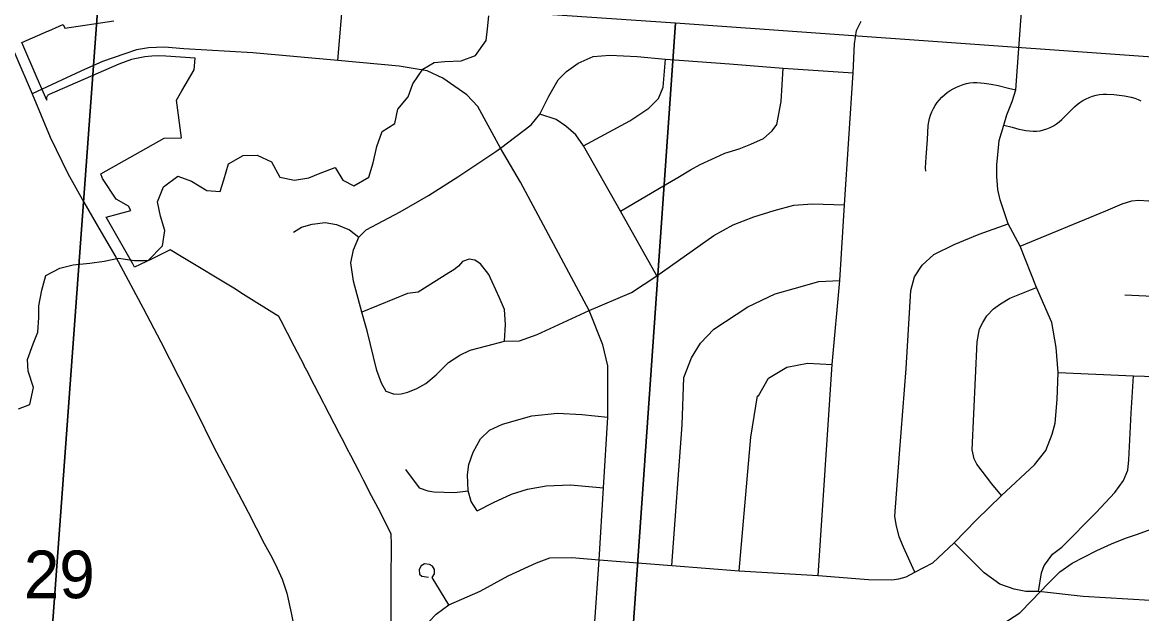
# Model space of a CAD drawing. Extents: x 0 to 34, y 0 to 26.1.
# Drawn here: x 25.117 to 26.1, y 16.628 to 17.147 of the extents above; entities that cross this region are included whole.
import ezdxf

# ---------------------------------------------------------------- set-up
doc = ezdxf.new("R2010")
doc.units = 0
for name, color, linetype in [('GM_X_Minor_River', 7, 'Continuous'), ('GM_X_Section', 7, 'Continuous'), ('GM_X_Section_Text', 7, 'Continuous'), ('GM_X_State_Route', 7, 'Continuous'), ('GM_X_Township_Road', 7, 'Continuous'), ('SC_Scratch1', 7, 'Continuous')]:
    doc.layers.add(name, color=color, linetype=linetype)

msp = doc.modelspace()

# ---------------------------------------------------------------- linework, layer by layer
at = {"layer": 'GM_X_Minor_River'}
for points in [[(25.11324, 16.80738), (25.12314, 16.81142), (25.12638, 16.82618), (25.12166, 16.84067), (25.12105, 16.85092), (25.12616, 16.86452), (25.13009, 16.87471), (25.13103, 16.88761), (25.13118, 16.89785), (25.13365, 16.91186), (25.13724, 16.92472), (25.14944, 16.93101), (25.16121, 16.93388), (25.17599, 16.93557), (25.18851, 16.93729), (25.20103, 16.93978), (25.215, 16.93769), (25.22712, 16.9379), (25.23979, 16.95063), (25.24187, 16.96427), (25.23789, 16.97685), (25.23542, 16.98941), (25.24053, 17.00262), (25.25315, 17.01194), (25.2652, 17.0076), (25.27871, 16.99944), (25.29042, 16.99852), (25.2936, 17.00872), (25.29758, 17.02271), (25.31055, 17.03012), (25.32267, 17.03034), (25.33545, 17.02447), (25.34283, 17.01108), (25.35565, 17.00824), (25.36817, 17.01035), (25.37807, 17.01439), (25.39139, 17.01952), (25.39804, 17.00842), (25.40781, 17.00335), (25.42079, 17.01114), (25.42475, 17.02361), (25.42798, 17.03799), (25.43271, 17.05121), (25.44378, 17.05827), (25.44623, 17.07076), (25.45547, 17.08164), (25.45942, 17.09298), (25.4683, 17.10576), (25.47823, 17.1117), (25.4877, 17.1127), (25.50209, 17.11326), (25.51465, 17.11803), (25.52392, 17.13118), (25.5252, 17.14142), (25.52612, 17.15279)], [(25.97756, 16.61855), (25.99245, 16.62822), (26.0032, 16.63908), (26.01742, 16.65406), (26.02778, 16.66417), (26.03849, 16.67199), (26.04878, 16.67716), (26.06022, 16.68308), (26.07317, 16.68897), (26.08535, 16.69374), (26.09599, 16.69739), (26.10779, 16.70178)]]:
    msp.add_lwpolyline(points, dxfattribs=at)
at = {"layer": 'GM_X_Section'}
for points in [[(24.68285, 17.21376), (25.18439, 17.18116), (25.11026, 16.16972), (24.60929, 16.20254)], [(25.18439, 17.18116), (25.69031, 17.14665), (25.6194, 16.13503), (25.11026, 16.16972)], [(26.19141, 17.11087), (26.11743, 16.09697), (25.6194, 16.13503), (25.69031, 17.14665)]]:
    msp.add_lwpolyline(points, close=True, dxfattribs=at)
at = {"layer": 'GM_X_State_Route'}
msp.add_lwpolyline([(25.09638, 17.151), (25.12531, 17.08427), (25.14115, 17.04605), (25.15657, 17.01437), (25.17051, 16.98903), (25.18592, 16.96263), (25.19859, 16.94067), (25.22275, 16.89595), (25.2383, 16.86634), (25.26912, 16.8053), (25.28412, 16.77489), (25.31495, 16.71661), (25.3291, 16.68915), (25.33586, 16.67648), (25.34051, 16.66762), (25.34473, 16.6579), (25.34874, 16.64565), (25.35254, 16.62813), (25.36331, 16.5747)], dxfattribs=at)
at = {"layer": 'GM_X_Township_Road'}
msp.add_line((26.13495, 16.90479), (26.08487, 16.9073), dxfattribs=at)
for points in [[(25.93503, 16.68984), (25.95463, 16.70992), (25.97645, 16.73139), (26.00555, 16.75831), (26.01526, 16.77085), (26.02093, 16.78535), (26.02345, 16.7948), (26.02534, 16.8156), (26.02628, 16.83955), (26.02444, 16.86148), (26.02059, 16.88329), (26.00725, 16.91408), (25.99289, 16.95051), (25.98238, 16.97), (25.97522, 16.99114), (25.97339, 17.00028), (25.97248, 17.01171), (25.97248, 17.02222), (25.97316, 17.03068), (25.97431, 17.04325), (25.97837, 17.05683), (25.98117, 17.06587), (25.98572, 17.07743), (25.98891, 17.08774), (26.00118, 17.2538)], [(25.39364, 17.11349), (25.39807, 17.16525)], [(25.81543, 16.66107), (25.82779, 16.84656), (25.83435, 16.92026), (25.83855, 16.98681), (25.84606, 17.1028), (25.84735, 17.12814), (25.84912, 17.13984), (25.85319, 17.14798)], [(25.61864, 16.61229), (25.62313, 16.67477), (25.62703, 16.73817), (25.63067, 16.8002), (25.63076, 16.84532), (25.62649, 16.86367), (25.61432, 16.89401), (25.55397, 17.00663), (25.53648, 17.03645), (25.51658, 17.07323), (25.50685, 17.0834), (25.48598, 17.09805), (25.47214, 17.10439), (25.44759, 17.10862), (25.39364, 17.11349), (25.31891, 17.12012), (25.25833, 17.12366), (25.24138, 17.12515), (25.22731, 17.12471), (25.21672, 17.12281), (25.20646, 17.11939), (25.18695, 17.11251), (25.16788, 17.10408), (25.12531, 17.08427)], [(25.5323, 17.03366), (25.53648, 17.03645), (25.56354, 17.05688), (25.57106, 17.06639), (25.57897, 17.08222), (25.58728, 17.09647), (25.59441, 17.10399), (25.6047, 17.11112), (25.61775, 17.11705), (25.63239, 17.11824), (25.65653, 17.11705), (25.68145, 17.11468), (25.73764, 17.11072), (25.78473, 17.10676), (25.84606, 17.1028)], [(25.60944, 17.03867), (25.6502, 17.06045), (25.66681, 17.07153), (25.67513, 17.08024), (25.67948, 17.09013), (25.68145, 17.11468)], [(25.64179, 16.9811), (25.68096, 17.0044), (25.69233, 17.01075), (25.70337, 17.01745), (25.71173, 17.02213), (25.7221, 17.02682), (25.73347, 17.03217), (25.74619, 17.03585), (25.75622, 17.03987), (25.76759, 17.04489), (25.77495, 17.05158), (25.7793, 17.05727), (25.78298, 17.07735), (25.78473, 17.10676)], [(25.91002, 17.01636), (25.90975, 17.01918), (25.91021, 17.02851), (25.91134, 17.04407), (25.91211, 17.05651), (25.91255, 17.05959), (25.91327, 17.06262), (25.91423, 17.06559), (25.91535, 17.0685), (25.91671, 17.0713), (25.9183, 17.07398), (25.9201, 17.07653), (25.92207, 17.07895), (25.92418, 17.08124), (25.92644, 17.08339), (25.92883, 17.08539), (25.93138, 17.08718), (25.93407, 17.08876), (25.93686, 17.09014), (25.93973, 17.09137), (25.94267, 17.09243), (25.94567, 17.09326), (25.94873, 17.09382), (25.95182, 17.0941), (25.95493, 17.09414), (25.95806, 17.09399), (25.96119, 17.09369), (25.96737, 17.09278), (25.97348, 17.09153), (25.98256, 17.0893), (25.98891, 17.08774)], [(25.97837, 17.05683), (25.98579, 17.05485), (25.99182, 17.05324), (25.99487, 17.05257), (25.99794, 17.05204), (26.00104, 17.05167), (26.00416, 17.05148), (26.00728, 17.05151), (26.01038, 17.05185), (26.01342, 17.0525), (26.0164, 17.05345), (26.01928, 17.05465), (26.02205, 17.05609), (26.02469, 17.05775), (26.02718, 17.05962), (26.02952, 17.06168), (26.03612, 17.06832), (26.04055, 17.07272), (26.04288, 17.0748), (26.04534, 17.07672), (26.04794, 17.07843), (26.0507, 17.07989), (26.05357, 17.08112), (26.05652, 17.08214), (26.05953, 17.08296), (26.06259, 17.08353), (26.0657, 17.08382), (26.06881, 17.08388), (26.07505, 17.08353), (26.08436, 17.08252), (26.08743, 17.082), (26.09047, 17.0813), (26.09346, 17.0804), (26.09639, 17.07932), (26.09873, 17.07807)], [(25.67367, 16.92433), (25.64179, 16.9811), (25.60944, 17.03867), (25.60271, 17.04817), (25.59401, 17.05569), (25.5853, 17.06163), (25.57106, 17.06639)], [(25.44281, 16.8205), (25.43607, 16.82267), (25.43198, 16.82989), (25.42788, 16.84121), (25.41946, 16.8759), (25.41464, 16.89252), (25.40742, 16.91974), (25.40501, 16.93576), (25.40742, 16.94732), (25.41223, 16.9584), (25.4185, 16.96467), (25.44835, 16.98057), (25.47339, 16.99502), (25.49891, 17.01139), (25.5323, 17.03366)], [(25.44281, 16.8205), (25.44932, 16.82074), (25.45509, 16.82219), (25.46304, 16.82532), (25.47098, 16.82966), (25.48014, 16.83736), (25.49097, 16.8482), (25.50084, 16.8547), (25.50975, 16.85904), (25.52443, 16.86289), (25.54009, 16.86699), (25.55308, 16.86723), (25.56874, 16.87277), (25.61432, 16.89401), (25.65166, 16.90976), (25.67367, 16.92433), (25.72379, 16.9599), (25.74081, 16.969), (25.75901, 16.97613), (25.77682, 16.98167), (25.79423, 16.98642), (25.81045, 16.98761), (25.83855, 16.98681)], [(25.99289, 16.95051), (26.06803, 16.9813), (26.08236, 16.98748), (26.09081, 16.99023), (26.09697, 16.99091), (26.10543, 16.99023), (26.11182, 16.98817), (26.12027, 16.98451), (26.12576, 16.9788), (26.13124, 16.97194), (26.13489, 16.96577), (26.13627, 16.96136), (26.13809, 16.95732), (26.13809, 16.9459), (26.13763, 16.9315), (26.13495, 16.90479), (26.13118, 16.83545)], [(25.35471, 16.9627), (25.36172, 16.96718), (25.37107, 16.96971), (25.38256, 16.97108), (25.39249, 16.96952), (25.40379, 16.96484), (25.41223, 16.9584)], [(25.90026, 16.66392), (25.89032, 16.68593), (25.88672, 16.69504), (25.88396, 16.70575), (25.88287, 16.71327), (25.88702, 16.76787), (25.89284, 16.84284), (25.89682, 16.91156), (25.89997, 16.92353), (25.9069, 16.93362), (25.91698, 16.94307), (25.93493, 16.95179), (25.95673, 16.96103), (25.98238, 16.97)], [(25.54009, 16.86699), (25.54081, 16.88144), (25.54009, 16.89469), (25.53527, 16.90553), (25.52612, 16.92552), (25.5189, 16.93492), (25.51384, 16.93805), (25.50902, 16.93901), (25.50324, 16.93684), (25.49949, 16.93287), (25.49557, 16.92974), (25.49121, 16.92697), (25.46424, 16.9101), (25.45485, 16.90891), (25.44329, 16.90408), (25.41464, 16.89252)], [(25.68694, 16.66978), (25.69607, 16.79354), (25.69758, 16.83494), (25.70425, 16.85222), (25.71222, 16.86524), (25.72382, 16.87735), (25.7536, 16.89704), (25.77783, 16.90866), (25.79448, 16.9132), (25.81618, 16.91926), (25.83435, 16.92026)], [(25.97645, 16.73139), (25.96809, 16.74158), (25.95476, 16.75875), (25.95245, 16.76341), (25.95063, 16.77141), (25.95519, 16.86635), (25.95724, 16.87764), (25.96006, 16.88329), (25.96365, 16.88919), (25.96955, 16.89535), (25.97545, 16.89971), (25.98366, 16.90484), (26.00725, 16.91408)], [(25.74621, 16.66515), (25.75619, 16.78261), (25.76218, 16.81879), (25.76302, 16.81892), (25.77177, 16.83444), (25.78792, 16.84403), (25.80609, 16.84756), (25.82779, 16.84656)], [(26.02628, 16.83955), (26.09243, 16.8364), (26.13118, 16.83545), (26.15013, 16.83416)], [(26.00882, 16.64699), (26.01173, 16.66335), (26.01391, 16.6699), (26.01609, 16.67245), (26.02119, 16.67973), (26.02955, 16.68591), (26.05973, 16.71647), (26.0761, 16.73394), (26.08373, 16.74449), (26.08739, 16.75352), (26.08834, 16.76265), (26.09023, 16.80363), (26.09243, 16.8364)], [(25.51591, 16.71776), (25.51085, 16.72596), (25.50796, 16.73549), (25.50738, 16.74936), (25.50883, 16.7586), (25.51258, 16.76929), (25.51893, 16.78113), (25.52673, 16.78864), (25.53828, 16.79413), (25.56397, 16.80135), (25.5865, 16.80366), (25.60786, 16.80251), (25.63067, 16.8002)], [(25.45311, 16.75427), (25.46494, 16.73809), (25.47274, 16.73549), (25.47794, 16.73462), (25.49612, 16.73405), (25.50796, 16.73549)], [(25.51591, 16.71776), (25.53023, 16.72514), (25.54629, 16.73252), (25.56019, 16.73687), (25.57668, 16.73991), (25.59795, 16.74078), (25.62703, 16.73817)], [(25.85577, 16.65786), (25.85981, 16.65754), (25.88003, 16.65718), (25.88642, 16.65824), (25.89281, 16.66002), (25.90026, 16.66392), (25.91623, 16.67209), (25.93503, 16.68984)], [(26.12665, 16.63785), (26.0481, 16.64262), (26.00882, 16.64699), (25.99791, 16.64699), (25.98773, 16.64917), (25.975, 16.65354), (25.96118, 16.66335), (25.93503, 16.68984)], [(25.491, 16.63528), (25.47658, 16.65926), (25.47859, 16.66263), (25.47859, 16.66631), (25.47691, 16.66916), (25.47423, 16.67084), (25.46987, 16.67134), (25.46685, 16.6695), (25.46501, 16.66631), (25.46551, 16.66212), (25.46752, 16.66044), (25.47339, 16.6596)], [(25.491, 16.63528), (25.51851, 16.64741), (25.54325, 16.66087), (25.568, 16.67216), (25.57972, 16.6765), (25.59925, 16.67694), (25.62313, 16.67477), (25.68694, 16.66978), (25.74621, 16.66515), (25.81543, 16.66107), (25.85577, 16.65786)], [(25.44602, 16.49107), (25.44262, 16.51465), (25.44321, 16.52465), (25.4469, 16.53707), (25.45529, 16.55552), (25.46468, 16.57196), (25.46803, 16.58378), (25.46836, 16.60911), (25.47105, 16.61582), (25.4739, 16.62052), (25.47993, 16.62723), (25.491, 16.63528)]]:
    msp.add_lwpolyline(points, dxfattribs=at)
at = {"layer": 'SC_Scratch1'}
msp.add_lwpolyline([(25.44052, 16.61981), (25.44054, 16.63717), (25.44057, 16.64705), (25.44059, 16.65652), (25.44066, 16.68838), (25.4405, 16.69776), (25.42893, 16.72014), (25.42332, 16.73099), (25.41617, 16.74483), (25.41258, 16.75178), (25.40494, 16.76657), (25.40198, 16.77231), (25.39878, 16.77848), (25.39515, 16.7855), (25.38203, 16.81089), (25.38139, 16.81213), (25.37313, 16.82812), (25.36638, 16.84118), (25.36422, 16.84536), (25.364, 16.84578), (25.35532, 16.86259), (25.34938, 16.87407), (25.34661, 16.87943), (25.34624, 16.88014), (25.34551, 16.88155), (25.34388, 16.88471), (25.34188, 16.88857), (25.32029, 16.9021), (25.31087, 16.908), (25.3023, 16.91338), (25.25757, 16.94044), (25.24655, 16.9471), (25.23068, 16.93933), (25.22016, 16.93418), (25.21517, 16.93182), (25.21348, 16.93478), (25.19017, 16.97589), (25.21185, 16.98184), (25.20984, 16.98553), (25.19907, 16.9918), (25.18711, 17.00984), (25.18565, 17.01381), (25.24108, 17.04531), (25.25644, 17.0457), (25.25196, 17.07863), (25.25676, 17.08685), (25.2675, 17.10524), (25.26824, 17.11548), (25.24274, 17.11734), (25.23655, 17.11756), (25.23036, 17.11734), (25.2242, 17.1167), (25.21835, 17.11568), (25.21258, 17.11426), (25.20692, 17.11247), (25.20139, 17.11029), (25.14007, 17.08365), (25.13955, 17.08337), (25.13907, 17.08301), (25.13866, 17.08258), (25.13832, 17.0821), (25.13806, 17.08156), (25.13789, 17.081), (25.1378, 17.08041), (25.13781, 17.07981), (25.13792, 17.07923), (25.13811, 17.07867), (25.12961, 17.09809), (25.11602, 17.12931), (25.1397, 17.1396), (25.13974, 17.13962), (25.149, 17.14364), (25.1525, 17.14516), (25.15397, 17.14178), (25.19708, 17.14838)], dxfattribs=at)

# ---------------------------------------------------------------- texts
at = {"layer": 'GM_X_Section_Text'}
msp.add_text('29', height=0.041856, rotation=0.00001, dxfattribs=at).set_placement((25.11792, 16.6411))

doc.saveas('drawing.dxf')
